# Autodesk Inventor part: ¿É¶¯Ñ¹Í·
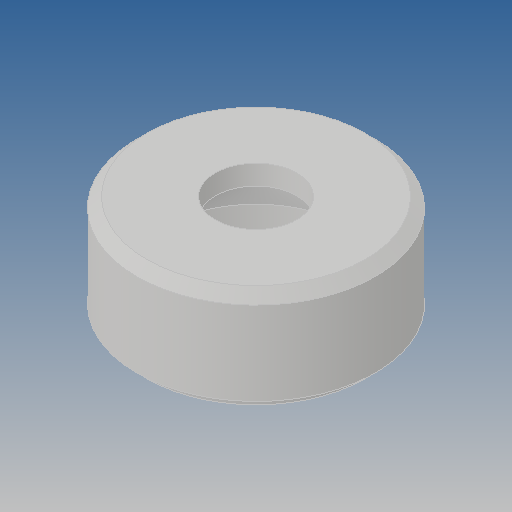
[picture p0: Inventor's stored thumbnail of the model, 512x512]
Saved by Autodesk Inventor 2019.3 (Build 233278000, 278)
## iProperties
Created: 2017-12
Part Number: ¿É¶¯Ñ¹Í·
Material: Ogólny
Document SubType Name: Modeling
Designer: Admin
Density: 1 g/cm^3
Appearance: Domyślna
Author: Admin
Revision Number: ÈÎºÎ
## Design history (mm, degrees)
feature "Ðý×ª1"
node "Bryła1"
